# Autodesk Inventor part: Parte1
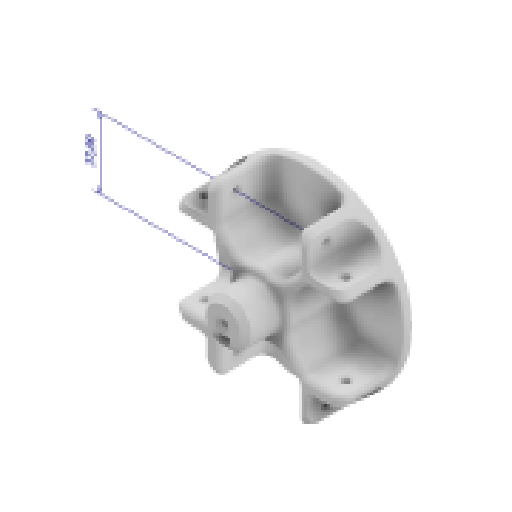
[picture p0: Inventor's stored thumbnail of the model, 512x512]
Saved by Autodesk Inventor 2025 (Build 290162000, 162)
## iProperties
Created: 2025-05
Part Number: Parte1
Material: Generico
Document SubType Name: Modeling
Designer: R5800u
Density: 1 g/cm^3
Appearance: Default
Author: R5800u
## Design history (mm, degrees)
node "Annotazioni"
  node "Quota lineare 1" dims "d0" = 100, "d1" = 45 deg, "d3" = 25, "d8" = 6, "d9" = 6, "d10" = 3, "d11" = 3, "d22" = 6, "d23" = 6, "d45" = 37 (derived)
sketch "Schizzo1" dims "d0" = 100
  geometry: L1 (0, 0)-(35.355, 35.355); L2 (0, 0)-(50, 0); L3 (20.572, 20.572)-(20.572, 45.572); L4 (20.572, 20.572)-(45.572, 20.572); L5 (0, 0)-(0, 44.829) reference; L6 (-20.572, 20.572)-(-20.572, 45.572); L7 (0, 0)-(-35.355, 35.355); L8 (-20.572, 20.572)-(-45.572, 20.572); L9 (0, 0)-(56.569, 0); L10 (26.572, 42.355)-(26.572, 26.572); L11 (26.572, 26.572)-(42.355, 26.572); L12 (-26.572, 42.355)-(-26.572, 26.572); L13 (-26.572, 26.572)-(-42.355, 26.572); L14 (-20.572, 24.815)-(0, 4.243); L15 (0, 4.243)-(20.572, 24.815); L16 (24.815, 20.572)-(0, -4.243); L17 (0, -4.243)-(-24.815, 20.572); L18 (20.572, -20.572)-(20.572, -45.572); L19 (0, -4.243)-(20.572, -24.815); L20 (26.572, -42.355)-(26.572, -26.572); L21 (24.815, -20.572)-(0, 4.243); L22 (0, 0)-(35.355, -35.355); L23 (26.572, -26.572)-(42.355, -26.572); L24 (20.572, -20.572)-(45.572, -20.572); L25 (0, 0)-(0, -44.829); L26 (-20.572, -24.815)-(0, -4.243); L27 (0, 4.243)-(-24.815, -20.572); L28 (0, 0)-(-35.355, -35.355); L29 (-20.572, -20.572)-(-20.572, -45.572); L30 (-26.572, -42.355)-(-26.572, -26.572); L31 (-26.572, -26.572)-(-42.355, -26.572); L32 (-20.572, -20.572)-(-45.572, -20.572); 3 further points
  constraints: 64 end point, 25 symmetric about line, 13 point on line, 3 vertical, 2 coincident, 2 horizontal, 1 equal length, 9 other
  dimensions: "d1" = 45 deg angle of L2 L1; "d3" = 25 distance of L3.start L4.end; "d8" = 6 distance between parallel lines of L3 L10; "d9" = 6 distance between parallel lines of L6 L12; "d10" = 3 distance between parallel lines of L7 L14; "d11" = 3 distance between parallel lines of L1 L16; "d22" = 6 distance between parallel lines of L4 L11; "d23" = 6 distance between parallel lines of L8 L13
extrude "Estrusione1" new body sketch "Schizzo1" stored distance "d4" = 75; taper "d5" = 0 deg
node "Piano di lavoro1"
sketch "Schizzo3" dims "d24" = 100
  geometry: L1 (0, 0)-(35.355, 35.355); L2 (0, 0)-(50, 0); L3 (20.572, 20.572)-(20.572, 45.572); L4 (20.572, 20.572)-(45.572, 20.572); L5 (0, 0)-(0, 44.829); L6 (-20.572, 20.572)-(-20.572, 45.572); L7 (0, 0)-(-35.355, 35.355); L8 (-20.572, 20.572)-(-45.572, 20.572); L9 (0, 0)-(56.569, 0); L10 (26.572, 42.355)-(26.572, 26.572); L11 (26.572, 26.572)-(42.355, 26.572); L12 (-26.572, 42.355)-(-26.572, 26.572); L13 (-26.572, 26.572)-(-42.355, 26.572); L14 (-20.572, 24.815)-(0, 4.243); L15 (0, 4.243)-(20.572, 24.815); L16 (24.815, 20.572)-(0, -4.243); L17 (0, -4.243)-(-24.815, 20.572); L18 (20.572, -20.572)-(20.572, -45.572); L19 (0, -4.243)-(20.572, -24.815); L20 (26.572, -42.355)-(26.572, -26.572); L21 (24.815, -20.572)-(0, 4.243); L22 (0, 0)-(35.355, -35.355); L23 (26.572, -26.572)-(42.355, -26.572); L24 (20.572, -20.572)-(45.572, -20.572); L25 (0, 0)-(0, -44.829); L26 (-20.572, -24.815)-(0, -4.243); L27 (0, 4.243)-(-24.815, -20.572); L28 (0, 0)-(-35.355, -35.355); L29 (-20.572, -20.572)-(-20.572, -45.572); L30 (-26.572, -42.355)-(-26.572, -26.572); L31 (-26.572, -26.572)-(-42.355, -26.572); L32 (-20.572, -20.572)-(-45.572, -20.572); 16 further points
  constraints: 64 end point, 25 symmetric about line, 13 point on line, 2 coincident, 2 horizontal, 2 parallel, 2 vertical, 1 equal length, 9 other
  dimensions: "d25" = 45 deg angle of L2 L1; "d26" = 25 distance of L3.start L4.end; "d27" = 6 distance between parallel lines of L3 L10; "d28" = 6 distance between parallel lines of L6 L12; "d29" = 3 distance between parallel lines of L7 L14; "d30" = 3 distance between parallel lines of L1 L16; "d31" = 6 distance between parallel lines of L4 L11; "d32" = 6 distance between parallel lines of L8 L13; "d41" = 3 distance between parallel lines of L1 L15; "d42" = 3 distance between parallel lines of L7 L17; "d63" = 25 distance of L18.start L24.end (derived); "d64" = 25 distance of L18.start L18.end (derived); "d65" = 41.14378 distance between parallel lines of L32 L8 (derived); "d66" = 41.14378 distance between parallel lines of L24 L4 (derived); "d67" = 41.14378 distance between parallel lines of L3 L6 (derived); "d68" = 41.14378 distance between parallel lines of L18 L29 (derived)
extrude "Estrusione4" cut sketch "Schizzo3" extent not by distance; stored distance "d33" = 30; taper "d34" = 0 deg
sketch "Schizzo4"
  geometry: L1 (45.572, 37.5)-(45.572, 3) reference; L2 (45.572, 20.25)-(0, 20.25); L3 (0, 3)-(0, 37.5) reference; C1 r 2 at (37, 20.25); 2 further points
  constraints: 2 end point, 2 midpoint, 1 centre point, 1 coincident, 1 point on line
  dimensions: "d36" = 37 horizontal distance of point (0, 0) point (37, 20.25); "d37" = 4 diameter of C1
extrude "Estrusione5" cut sketch "Schizzo4" extent not by distance; stored distance "d38" = 0; taper "d39" = 0 deg
pattern_circular "Serie circolare1" dims angle "d47" = 360 deg
fillet "Raccordo1" dims "d49" = 2
pattern_circular "Serie circolare2" dims angle "d51" = 360 deg
sketch "Schizzo5"
  geometry: C1 r 50 at (0, 0) reference; 1 further point
extrude "Estrusione6" cut sketch "Schizzo5" distance "d53" = 36; taper "d54" = 0 deg
sketch "Schizzo6"
  geometry: C1 r 16 at (0, 0); 1 further point
  constraints: 1 centre point, 1 coincident
  dimensions: "d55" = 32 diameter of C1
extrude "Estrusione7" join sketch "Schizzo6" stored distance "d56" = 36; taper "d57" = 0 deg
fillet "Raccordo2" dims "d58" = 10
fillet "Raccordo3" dims "d59" = 3
pattern_circular "Serie circolare3" dims angle "d61" = 360 deg
sketch "Schizzo7"
  geometry: C1 r 2.5 at (0, 0); 1 further point
  constraints: 1 centre point, 1 coincident
  dimensions: "d69" = 5 diameter of C1
extrude "Estrusione8" cut sketch "Schizzo7" extent not by distance; stored distance "d70" = 10; taper "d71" = 0 deg
sketch "Schizzo8"
  geometry: L1 (18.043, 13.8)-(23.936, 19.693) reference; L2 (26.057, 20.572)-(42.362, 20.572) reference; L3 (42.355, 26.572)-(26.572, 26.572) reference; L4 (26.572, 26.572)-(26.572, 42.355) reference; L5 (20.572, 42.362)-(20.572, 26.057) reference; L6 (19.693, 23.936)-(13.8, 18.043) reference; L7 (-13.8, 18.043)-(-19.693, 23.936) reference; L8 (-20.572, 26.057)-(-20.572, 42.362) reference; L9 (-26.572, 42.355)-(-26.572, 26.572) reference; L10 (-26.572, 26.572)-(-42.355, 26.572) reference; L11 (-42.362, 20.572)-(-26.057, 20.572) reference; L12 (-23.936, 19.693)-(-18.043, 13.8) reference; L13 (-18.043, -13.8)-(-23.936, -19.693) reference; L14 (-26.057, -20.572)-(-42.362, -20.572) reference; L15 (-42.355, -26.572)-(-26.572, -26.572) reference; L16 (-26.572, -26.572)-(-26.572, -42.355) reference; L17 (-20.572, -42.362)-(-20.572, -26.057) reference; L18 (-19.693, -23.936)-(-13.8, -18.043) reference; L19 (13.8, -18.043)-(19.693, -23.936) reference; L20 (20.572, -26.057)-(20.572, -42.362) reference; L21 (26.572, -42.355)-(26.572, -26.572) reference; L22 (26.572, -26.572)-(42.355, -26.572) reference; L23 (42.362, -20.572)-(26.057, -20.572) reference; L24 (23.936, -19.693)-(18.043, -13.8) reference; C1 r 2.5 at (0, 0) reference; A1 r 3 centre (26.057, 17.572) between (26.057, 20.572) and (23.936, 19.693) reference; A2 r 50 centre (0, 0) between (44.127, 23.512) and (42.355, 26.572) reference; A3 r 50 centre (0, 0) between (26.572, 42.355) and (23.512, 44.127) reference; A4 r 2 centre (22.572, 42.362) between (23.512, 44.127) and (20.572, 42.362) reference; A5 r 3 centre (17.572, 26.057) between (19.693, 23.936) and (20.572, 26.057) reference; A6 r 10 centre (6.729, 25.114) between (4.141, 15.455) and (13.8, 18.043) reference; A7 r 16 centre (0, 0) between (4.141, 15.455) and (-4.141, 15.455) reference; A8 r 10 centre (-6.729, 25.114) between (-13.8, 18.043) and (-4.141, 15.455) reference; A9 r 3 centre (-17.572, 26.057) between (-20.572, 26.057) and (-19.693, 23.936) reference; A10 r 2 centre (-22.572, 42.362) between (-20.572, 42.362) and (-23.512, 44.127) reference; A11 r 50 centre (0, 0) between (-23.512, 44.127) and (-26.572, 42.355) reference; A12 r 50 centre (0, 0) between (-42.355, 26.572) and (-44.127, 23.512) reference; A13 r 3 centre (-26.057, 17.572) between (-23.936, 19.693) and (-26.057, 20.572) reference; A14 r 10 centre (-25.114, 6.729) between (-15.455, 4.141) and (-18.043, 13.8) reference; A15 r 16 centre (0, 0) between (-15.455, 4.141) and (-15.455, -4.141) reference; A16 r 10 centre (-25.114, -6.729) between (-18.043, -13.8) and (-15.455, -4.141) reference; A17 r 3 centre (-26.057, -17.572) between (-26.057, -20.572) and (-23.936, -19.693) reference; A18 r 50 centre (0, 0) between (-44.127, -23.512) and (-42.355, -26.572) reference; A19 r 50 centre (0, 0) between (-26.572, -42.355) and (-23.512, -44.127) reference; A20 r 3 centre (-17.572, -26.057) between (-19.693, -23.936) and (-20.572, -26.057) reference; A21 r 10 centre (-6.729, -25.114) between (-4.141, -15.455) and (-13.8, -18.043) reference; A22 r 16 centre (0, 0) between (-4.141, -15.455) and (4.141, -15.455) reference; A23 r 10 centre (6.729, -25.114) between (13.8, -18.043) and (4.141, -15.455) reference; A24 r 3 centre (17.572, -26.057) between (20.572, -26.057) and (19.693, -23.936) reference; A25 r 50 centre (0, 0) between (23.512, -44.127) and (26.572, -42.355) reference; A26 r 50 centre (0, 0) between (42.355, -26.572) and (44.127, -23.512) reference; A27 r 3 centre (26.057, -17.572) between (23.936, -19.693) and (26.057, -20.572) reference; A28 r 10 centre (25.114, -6.729) between (15.455, -4.141) and (18.043, -13.8) reference; A29 r 16 centre (0, 0) between (15.455, -4.141) and (15.455, 4.141) reference; A30 r 10 centre (25.114, 6.729) between (18.043, 13.8) and (15.455, 4.141) reference; A31 r 2 centre (42.362, 22.572) between (42.362, 20.572) and (44.127, 23.512) reference; A32 r 2 centre (-42.362, 22.572) between (-44.127, 23.512) and (-42.362, 20.572) reference; A33 r 2 centre (-42.362, -22.572) between (-42.362, -20.572) and (-44.127, -23.512) reference; A34 r 2 centre (-22.572, -42.362) between (-23.512, -44.127) and (-20.572, -42.362) reference; A35 r 2 centre (22.572, -42.362) between (20.572, -42.362) and (23.512, -44.127) reference; A36 r 2 centre (42.362, -22.572) between (44.127, -23.512) and (42.362, -20.572) reference; 1 further point
extrude "Estrusione9" cut sketch "Schizzo8" distance "d72" = 8; taper "d73" = 0 deg
fillet "Raccordo5" dims "d75" = 5
fillet "Raccordo6" dims "d76" = 3
fillet "Raccordo7" dims "d77" = 3
fillet "Raccordo8" dims "d78" = 8.5
fillet "Raccordo9" dims "d79" = 5
sketch "Schizzo10"
  geometry: C1 r 2.5 at (0, 0) reference; C2 r 12 at (0, 0); 1 further point
  constraints: 1 centre point, 1 coincident
  dimensions: "d84" = 24 diameter of C2
extrude "Estrusione11" join sketch "Schizzo10" distance "d85" = 18; taper "d86" = 0 deg
sketch "Schizzo11"
  geometry: L1 (1.356, -2.1)-(-1.356, -2.1); A1 r 2.5 centre (0, 0) between (1.356, -2.1) and (-1.356, -2.1) reference; 1 further point
  constraints: 2 end point, 2 point on circle, 1 horizontal
  dimensions: "d88" = 2.1 distance from line of point (0, 0) L1
node "Piano di lavoro3"
extrude "Estrusione12" join sketch "Schizzo11" stored distance "d89" = 15; taper "d90" = 0 deg
sketch "Schizzo12"
  geometry: L1 (7.07, -12.504)-(-7.07, -12.504); L2 (-7.07, -12.504)-(-7.07, -11.496); L3 (-7.07, -11.496)-(7.07, -11.496); L4 (7.07, -11.496)-(7.07, -12.504); L5 (7.07, -12.504)-(-7.07, -11.496); L6 (-7.07, -12.504)-(7.07, -11.496); A1 r 12 centre (0, 0) between (6.017, -10.382) and (-6.017, -10.382) reference; 4 further points
  constraints: 12 end point, 3 point on circle, 2 midpoint, 2 parallel, 1 horizontal, 1 perpendicular
extrude "Estrusione13" cut sketch "Schizzo12" distance "d91" = 16; taper "d92" = 0 deg
sketch "Schizzo16"
  geometry: L1 (3.55, -8.45)-(-3.55, -8.45); L2 (-3.55, -8.45)-(-3.55, -4.55); L3 (-3.55, -4.55)-(3.55, -4.55); L4 (3.55, -4.55)-(3.55, -8.45); L5 (3.55, -8.45)-(-3.55, -4.55); L6 (-3.55, -8.45)-(3.55, -4.55); 2 further points
  constraints: 12 end point, 2 midpoint, 2 parallel, 1 horizontal, 1 perpendicular
  dimensions: "d105" = 7.1 distance of L2.end L3.end; "d106" = 3.9 distance of L1.end L2.end; "d109" = 6.5 distance of point (0, 0) point (0, -6.5)
extrude "Estrusione15" cut sketch "Schizzo16" stored distance "d107" = 14; taper "d108" = 0 deg
sketch "Schizzo17"
  geometry: L1 (0, 0)-(6.88, 0) reference; 2 further points
  dimensions: "d110" = 10 distance from line of L1 point (3.44, -10)
hole "Foro2" sketch "Schizzo17" at (3.44, -10) diameter "d111" = 4.3; stored, may be unused: countersink angle "d115" = 90 deg, drill point angle "d117" = 118 deg; dims "d112" = 6, "d113" = 4, "d114" = 2, "d116" = 11.5
fillet "Raccordo12" dims "d118" = 2
chamfer "Smusso1" distance "d119" = 3; stored, may be unused: second distance "d120" = 2, angle "d121" = 45 deg
fillet "Raccordo13" dims "d122" = 1
feature "׬耀׮耀װ耀ײ耀״耀׶耀׸耀׺耀" dims "d0" = 100, "d1" = 45 deg, "d3" = 25, "d4" = 75, "d5" = 0, "d8" = 6, "d9" = 6, "d10" = 3, "d11" = 3, "d12" = 3, "d18" = 2, "d19" = 2, "d22" = 6, "d23" = 6, "d24" = 100, "d25" = 45 deg, "d26" = 25, "d27" = 6, "d28" = 6, "d29" = 3, "d30" = 3, "d31" = 6, "d32" = 6, "d33" = 30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
feature "޸耀޺耀޼耀޾耀߀耀߂耀߄耀߆耀" dims "d0" = 100, "d1" = 45 deg, "d3" = 25, "d4" = 75, "d5" = 0, "d8" = 6, "d9" = 6, "d10" = 3, "d11" = 3, "d12" = 3, "d18" = 2, "d19" = 2, "d22" = 6, "d23" = 6, "d24" = 100, "d25" = 45 deg, "d26" = 25, "d27" = 6, "d28" = 6, "d29" = 3, "d30" = 3, "d31" = 6, "d32" = 6, "d33" = 30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
node "Solido1"
node "Linea chiusa proiettata1"
